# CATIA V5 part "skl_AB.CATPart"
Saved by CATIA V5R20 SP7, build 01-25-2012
Part number: skl_AB
Publications: "Point A", "PoinT B", "Plan.1", "Droite.1", "Droite.2", "Droite.3"
Bounding box of the stored display mesh (mm): x 0 to 10, y -29.623 to 0, z 0 to 4.744
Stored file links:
  U:\IAO-Thinkmotion\TRAVAIL A RENDRE\skl_AB.CATPart
  U:\IAO-Thinkmotion\TRAVAIL A RENDRE\skl_levier2bras.CATProduct
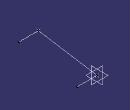
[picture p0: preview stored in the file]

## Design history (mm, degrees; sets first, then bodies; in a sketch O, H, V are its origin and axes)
Set1
  Point1 "Point A": linked copy from another document
  Point2 "PoinT B": linked copy from another document
  Plane1: linked copy from another document
Set2
  Line1 "Droite AB": type PtPt, FirstPoint Point1, SecondPoint Point2
  Line2 "Axe_AB_A": type Normal, RefPoint Point1, RefSkin Plane1, Start 0, End 10
  Line3 "Axe_AB_B": type Normal, RefPoint Point2, RefSkin Plane1, Start 0, End 10
Body1 (main body)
